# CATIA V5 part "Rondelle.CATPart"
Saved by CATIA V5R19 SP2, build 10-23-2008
Part number: Rondelle
Bounding box of the stored display mesh (mm): x 0 to 1, y -2 to 2, z -2 to 2
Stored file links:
  G:\EU_thinkMotion\CFAO_2010\MMS_groupe3\MMS_groupe3\A reprendre\lletoffe\lletoffe_Thinkmotion_CFAO\Modèle Catia\Rondelle.CATPart
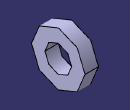
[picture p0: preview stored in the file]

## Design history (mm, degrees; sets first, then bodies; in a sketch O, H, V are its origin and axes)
Parameters
  Epaisseur = 1 mm
Set1
  Point1: (0, 0, 0)
  Point2: (1, 0, 0)
  Line1: type PtPt, FirstPoint Point1, SecondPoint Point2, Start 10, End 10
  Plane1: type Offset, RefPlane yz-plane, Offset 1 {= Epaisseur}
  Sketch1 on yz-plane, origin (0, 0, 0), H (0, 1, 0), V (0, 0, 1)
    circle A1 centre (0, 0) radius 2
    circle A2 centre (0, 0) radius 1
    reference projected point E1 (0, 0) from Line1
    radius A2 = 1
    radius A1 = 2
    concentricity: A1 E1
Body1 (main body)
  Pad1: profile Sketch1, direction (1, 0, 0), up to Plane1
